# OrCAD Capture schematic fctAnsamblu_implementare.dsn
size B
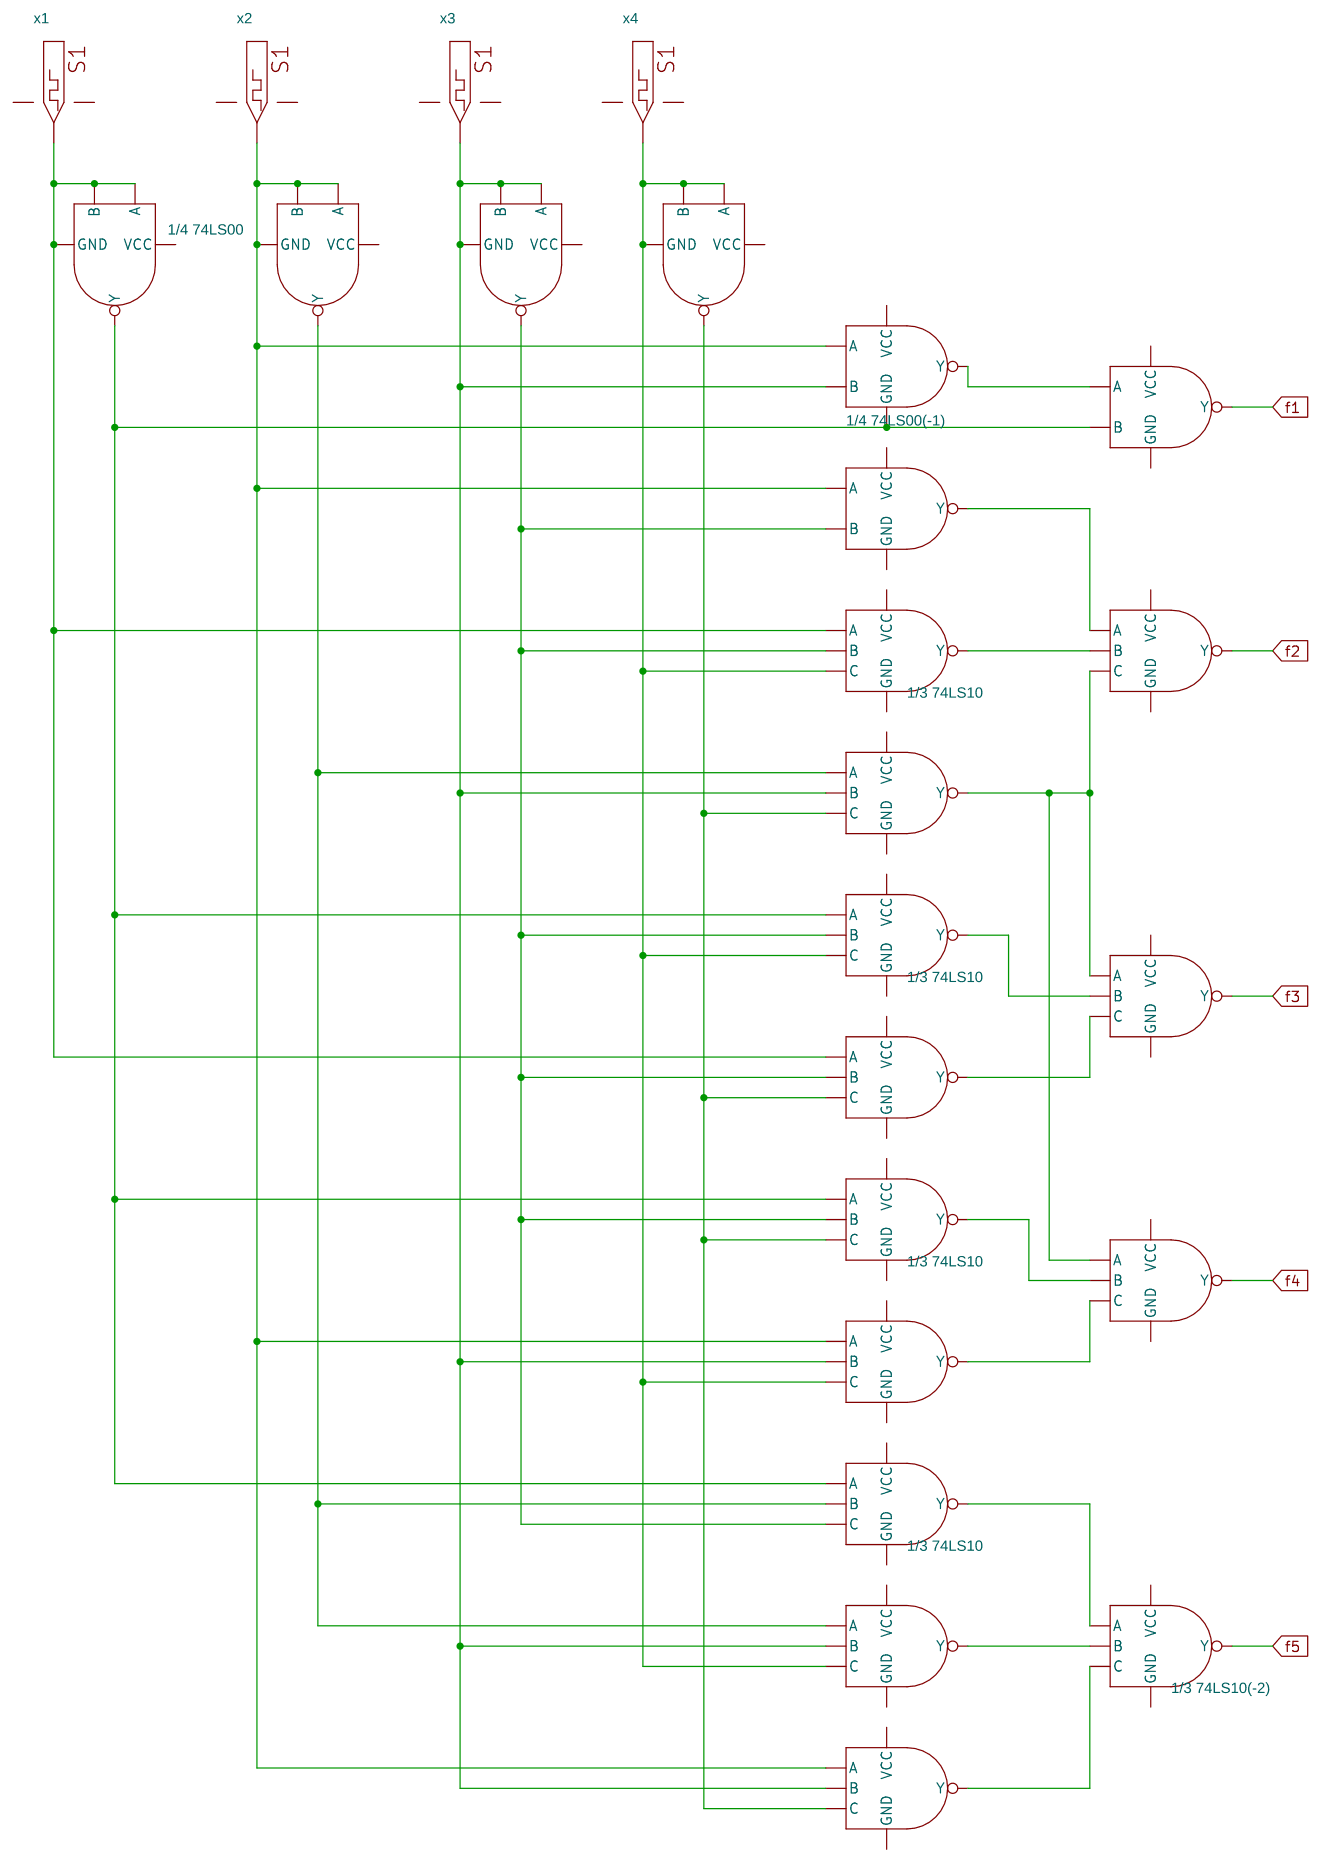
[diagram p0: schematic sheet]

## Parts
U13  1/4 74LS00  [DIP.100/14/W.300/L.800]  (sections A,B,C,D)
U14  1/4 74LS00(-1)  [DIP.100/14/W.300/L.800]  (sections A,B,C)
U15  1/3 74LS10  [DIP.100/14/W.300/L.800]  (sections A,B,C)
U16  1/4 74LS10  [DIP.100/14/W.300/L.800]  (section B)
U17  1/4 74LS10  [DIP.100/14/W.300/L.800]  (section B)
U19  1/4 74LS10  [DIP.100/14/W.300/L.800]  (section B)
U20  1/4 74LS10  [DIP.100/14/W.300/L.800]  (section B)
U22  1/4 74LS10  [DIP.100/14/W.300/L.800]  (section B)
U23  1/4 74LS10  [DIP.100/14/W.300/L.800]  (section B)
U25  1/3 74LS10  [DIP.100/14/W.300/L.800]  (section B)
U26  1/3 74LS10  [DIP.100/14/W.300/L.800]  (section B)
U27  1/3 74LS10  [DIP.100/14/W.300/L.800]  (section B)
U28  1/3 74LS10(-2)  [DIP.100/14/W.300/L.800]  (section B)
x1  DigStim1
x2  DigStim1
x3  DigStim1
x4  DigStim1

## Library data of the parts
U13 U14 = 74LS00
U15-U17 U19 U20 U22 U23 U25-U28 = 74LS10
x1-x4 = DigStim1

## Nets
GND: U13.7(GND) U14.7(GND) U15.7(GND) U16.7(GND) U17.7(GND) U19.7(GND) U20.7(GND) U22.7(GND) U23.7(GND) U25.7(GND) U26.7(GND) U27.7(GND) U28.7(GND) x1.3(GND) x2.3(GND) x3.3(GND) x4.3(GND)
VCC: U13.14(VCC) U14.14(VCC) U15.14(VCC) U16.14(VCC) U17.14(VCC) U19.14(VCC) U20.14(VCC) U22.14(VCC) U23.14(VCC) U25.14(VCC) U26.14(VCC) U27.14(VCC) U28.14(VCC) x1.2(VCC) x2.2(VCC) x3.2(VCC) x4.2(VCC)
f1: U14.6(Y)
f2: U15.8(Y)
f3: U16.6(Y)
f4: U19.6(Y)
f5: U28.6(Y)
N15941: U13.12(A) U13.13(B) U15.5(C) U20.5(C) U22.5(C) U25.5(C) x4.OUT
N15953: U13.9(A) U13.10(B) U14.2(B) U15.2(B) U20.4(B) U22.4(B) U23.4(B) x3.OUT
N15965: U13.4(A) U13.5(B) U14.1(A) U14.9(A) U20.3(A) U23.3(A) x2.OUT
N15977: U13.1(A) U13.2(B) U15.3(A) U17.3(A) x1.OUT
N16279: U13.8(Y) U14.10(B) U15.4(B) U17.4(B) U25.4(B) U26.4(B) U27.5(C)
N16524: U13.6(Y) U15.1(A) U22.3(A) U27.4(B)
N16545: U13.11(Y) U15.13(C) U17.5(C) U23.5(C) U26.5(C)
N16598: U15.11(C) U15.12(Y) U16.3(A) U19.3(A)
N16605: U14.8(Y) U15.9(A)
N16636: U15.6(Y) U15.10(B)
N16652: U13.3(Y) U14.5(B) U25.3(A) U26.3(A) U27.3(A)
N16820: U16.5(C) U17.6(Y)
N16827: U16.4(B) U25.6(Y)
N16888: U14.3(Y) U14.4(A)
N17184: U19.4(B) U26.6(Y)
N17196: U19.5(C) U20.6(Y)
N17510: U22.6(Y) U28.4(B)
N17514: U27.6(Y) U28.3(A)
N17521: U23.6(Y) U28.5(C)
